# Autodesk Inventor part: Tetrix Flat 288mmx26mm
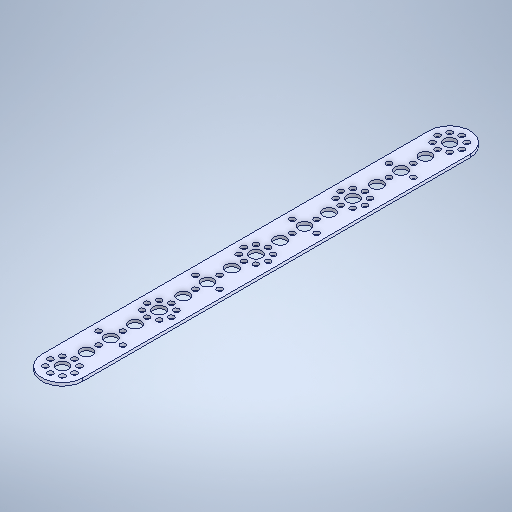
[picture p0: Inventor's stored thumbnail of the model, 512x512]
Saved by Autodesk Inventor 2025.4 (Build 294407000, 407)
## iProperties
Created: 2021-10
Part Number: Tetrix Flat 288mmx26mm
Material: Genérico
Document SubType Name: Modeling
Designer: usuario
Density: 1 g/cm^3
Appearance: Valor por defecto
Author: usuario
Sending System: SolidWorks 2016
Last Author: LENOVO
Last Saved: 2021-10-23
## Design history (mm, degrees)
feature "Boss-Extrude1"
node "Plane1"
node "Sólido1"
